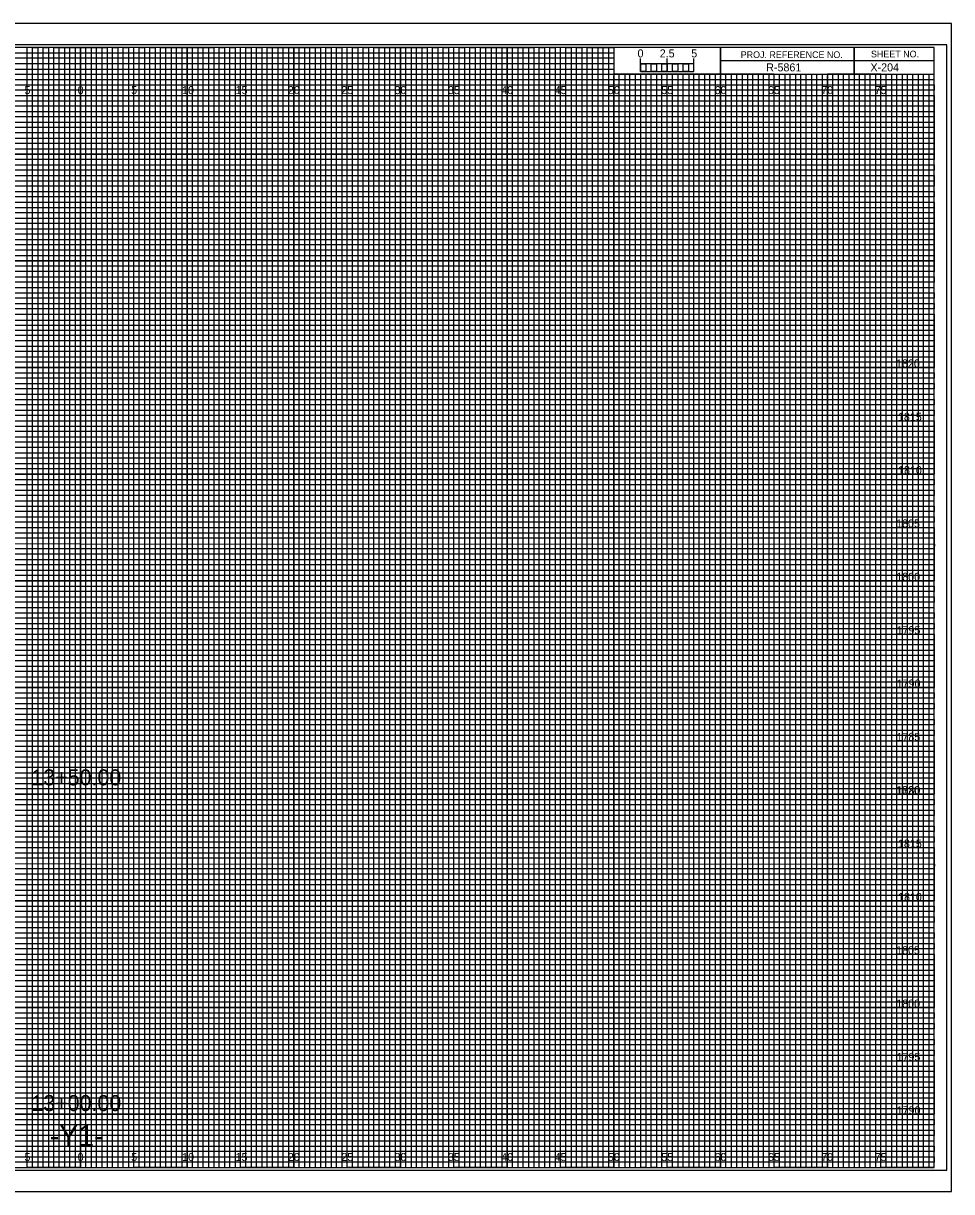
# Model space of a CAD drawing. Extents: x -7 to 162, y -2 to 767.
# Drawn here: x 74.6 to 161.7, y 327.7 to 437.2 of the extents above; entities that cross this region are included whole.
import ezdxf

# ---------------------------------------------------------------- set-up
doc = ezdxf.new("R2010")
doc.units = 0
for name, color, linetype in [('Prop Grid Mask', 7, 'Continuous'), ('Prop XS Alignment Label', 7, 'Continuous'), ('Prop XS Bar Scale Labels', 7, 'Continuous'), ('Prop XS Elevation Labels', 7, 'Continuous'), ('Prop XS Project Number', 7, 'Continuous'), ('Prop XS Sheet Number', 7, 'Continuous'), ('Prop XS Station Labels', 7, 'Continuous'), ('Sheet Cross Section CELL', 7, 'Continuous'), ('Sheet Cross Section Grid Major CELL', 7, 'Continuous'), ('Sheet Cross Section Grid Middle CELL', 7, 'Continuous'), ('Sheet Cross Section Grid Minor 1 CELL', 7, 'Continuous'), ('Sheet Cross Section Grid Minor 2 CELL', 7, 'Continuous'), ('Sheet Cross Section Scale CELL', 7, 'Continuous'), ('Sheet Cutting Line CELL', 7, 'Continuous'), ('Sheet DOT Grid CELL', 7, 'Continuous'), ('Sheet Plot Border Inside CELL', 7, 'Continuous'), ('Sheet Plot Border Outside CELL', 7, 'Continuous')]:
    doc.layers.add(name, color=color, linetype=linetype)

msp = doc.modelspace()

# ---------------------------------------------------------------- linework, layer by layer
at = {"layer": 'Sheet Cross Section CELL'}
for p, q in [((152.5, 435), (152.5, 432.5)), ((152.5, 432.5), (152.5, 435)), ((160, 433.75), (140, 433.75)), ((140, 433.75), (140, 432.5)), ((140, 432.5), (160, 432.5))]:
    msp.add_line(p, q, dxfattribs=at)
for points in [[(160, 435), (0, 435), (0, 330), (160, 330)], [(140, 435), (130, 435), (130, 432.51), (140, 432.51)], [(160, 435), (140, 435), (140, 432.5), (160, 432.5)]]:
    msp.add_lwpolyline(points, close=True, dxfattribs=at)
at = {"layer": 'Sheet Cross Section Grid Major CELL'}
for p, q in [((75, 435), (70, 435)), ((75, 330), (75, 435)), ((85, 435), (80, 435)), ((80, 435), (80, 330)), ((85, 330), (85, 435)), ((95, 435), (90, 435)), ((90, 435), (90, 330)), ((95, 330), (95, 435)), ((105, 435), (100, 435)), ((100, 435), (100, 330)), ((105, 330), (105, 435)), ((115, 435), (110, 435)), ((110, 435), (110, 330)), ((115, 330), (115, 435)), ((125, 435), (120, 435)), ((120, 435), (120, 330)), ((125, 330), (125, 435)), ((130, 435), (130, 330)), ((135, 330), (135, 432.5)), ((145, 432.5), (140, 432.5)), ((140, 432.5), (140, 330)), ((145, 330), (145, 432.5)), ((155, 432.5), (150, 432.5)), ((150, 432.5), (150, 330)), ((155, 330), (155, 432.5)), ((80, 330), (75, 330)), ((90, 330), (85, 330)), ((100, 330), (95, 330)), ((110, 330), (105, 330)), ((120, 330), (115, 330)), ((130, 330), (125, 330)), ((140, 330), (135, 330)), ((150, 330), (145, 330)), ((160, 330), (155, 330)), ((160, 330), (160, 330))]:
    msp.add_line(p, q, dxfattribs=at)
for points in [[(0, 430), (160, 430), (160, 425), (0, 425)], [(0, 420), (160, 420), (160, 415), (0, 415)], [(0, 410), (160, 410), (160, 405), (0, 405)], [(0, 400), (160, 400), (160, 395), (0, 395)], [(0, 390), (160, 390), (160, 385), (0, 385)], [(0, 380), (160, 380), (160, 375), (0, 375)], [(0, 370), (160, 370), (160, 365), (0, 365)], [(0, 360), (160, 360), (160, 355), (0, 355)], [(0, 350), (160, 350), (160, 345), (0, 345)], [(0, 340), (160, 340), (160, 335), (0, 335)]]:
    msp.add_lwpolyline(points, dxfattribs=at)
at = {"layer": 'Sheet Cross Section Grid Middle CELL'}
for points in [[(72.5, 330), (77.5, 330), (77.5, 435), (82.5, 435), (82.5, 330), (87.5, 330), (87.5, 435), (92.5, 435), (92.5, 330), (97.5, 330), (97.5, 435), (102.5, 435), (102.5, 330), (107.5, 330), (107.5, 435), (112.5, 435), (112.5, 330), (117.5, 330), (117.5, 435), (122.5, 435), (122.5, 330), (127.5, 330), (127.5, 435), (129.97, 435), (130, 435), (130, 432.5), (132.5, 432.5), (132.5, 330), (137.5, 330), (137.5, 432.5), (142.5, 432.5), (142.5, 330), (147.5, 330), (147.5, 432.5), (152.5, 432.5), (152.5, 330), (157.5, 330), (157.5, 432.5)], [(0, 432.5), (137.5, 432.5)], [(0, 422.5), (160, 422.5), (160, 427.5), (0, 427.5)], [(0, 412.5), (160, 412.5), (160, 417.5), (0, 417.5)], [(0, 402.5), (160, 402.5), (160, 407.5), (0, 407.5)], [(0, 392.5), (160, 392.5), (160, 397.5), (0, 397.5)], [(0, 382.5), (160, 382.5), (160, 387.5), (0, 387.5)], [(0, 372.5), (160, 372.5), (160, 377.5), (0, 377.5)], [(0, 362.5), (160, 362.5), (160, 367.5), (0, 367.5)], [(0, 352.5), (160, 352.5), (160, 357.5), (0, 357.5)], [(0, 342.5), (160, 342.5), (160, 347.5), (0, 347.5)], [(0, 332.5), (160, 332.5), (160, 337.5), (0, 337.5)]]:
    msp.add_lwpolyline(points, dxfattribs=at)
at = {"layer": 'Sheet Cross Section Grid Minor 1 CELL'}
for p, q in [((0, 434.5), (130, 434.5)), ((130, 433.99), (0, 433.99)), ((130, 434.5), (130, 433.99)), ((0, 433.5), (130, 433.5)), ((130, 432.94), (0, 432.94)), ((130, 433.5), (130, 432.94)), ((0, 432), (160, 432))]:
    msp.add_line(p, q, dxfattribs=at)
for points in [[(0, 431.5), (135, 431.5), (160, 431.5), (160, 431), (0, 431)], [(0, 430.5), (160, 430.5), (160, 429.5), (0, 429.5)], [(0, 429), (160, 429), (160, 428.5), (0, 428.49)], [(0, 428), (160, 428), (160, 427), (0, 427)], [(0, 426.5), (160, 426.5), (160, 426), (0, 426)], [(0, 425.5), (160, 425.5), (160, 424.5), (0, 424.5)], [(0, 424), (160, 424), (160, 423.5), (0, 423.5)], [(0, 423), (160, 423), (160, 422), (0, 422)], [(0, 421.5), (160, 421.5), (160, 421), (0, 421)], [(0, 420.5), (160, 420.5), (160, 419.5), (0, 419.5)], [(0, 419), (160, 419), (160, 418.5), (0, 418.5)], [(0, 418), (160, 418), (160, 416.98), (160, 416.5), (160, 416), (0, 416)], [(0, 417), (160, 417), (160, 416.5), (0, 416.5)], [(0, 415.5), (160, 415.5), (160, 414.5), (0, 414.51)], [(0, 414.51), (160, 414.5), (160, 414), (0, 414)], [(0, 413.5), (160, 413.5), (160, 413), (0, 413)], [(0, 412), (160, 412), (160, 411.5), (0, 411.5)], [(0, 411), (160, 411), (160, 410.5), (0, 410.5)], [(-0.04, 409.44), (160, 409.44), (160, 408.94), (-0.04, 408.94)], [(0, 408.5), (160, 408.5), (160, 408), (0, 408)], [(0, 407), (160, 407), (160, 406.5), (0, 406.5)], [(0, 406), (160, 406), (160, 405.5), (0, 405.5)], [(0, 404.5), (160, 404.5), (160, 404), (0, 404)], [(0, 403.5), (160, 403.5), (160, 403), (0, 403)], [(0, 402), (160, 402), (160, 401.5), (0, 401.5)], [(0, 401), (160, 401), (160, 400.5), (0, 400.5)], [(0, 399.5), (160, 399.5), (160, 398.99), (0, 399)], [(0, 398.5), (160, 398.5), (160, 398), (0, 398)], [(0, 397), (160, 397), (160, 396.5), (0, 396.5)], [(0, 396), (160, 396), (160, 395.5), (0, 395.5)], [(0, 394.5), (160, 394.5), (160, 394), (0, 394)], [(0, 393.5), (160, 393.5), (160, 393), (0, 393)], [(0, 392), (160, 392), (160, 391.5), (0, 391.5)], [(0, 391), (160, 391), (160, 390.5), (0, 390.5)], [(0, 389.5), (160, 389.5), (160, 389), (0, 389)], [(0, 388.5), (160.03, 388.45), (160, 388), (0, 388)], [(0, 387), (160, 387), (160, 386.5), (0, 386.5)], [(0, 386), (160, 386), (160, 385.5), (0, 385.5)], [(0, 384.5), (160, 384.5), (160, 384), (0, 384)], [(0, 383.5), (160, 383.5), (160, 383), (0, 383)], [(0, 382), (160, 382), (160, 381.5), (0, 381.5)], [(0, 381), (160, 381), (160, 380.5), (0, 380.5)], [(0, 379.5), (160, 379.5), (160, 379), (0, 379)], [(0, 378.5), (160, 378.5), (160, 378), (0, 378)], [(0, 377), (160, 377), (160, 376.5), (0, 376.5)], [(0, 376), (160, 376), (160, 375.5), (0, 375.5)], [(0, 374.5), (160, 374.5), (160, 374), (0, 374)], [(0, 373.5), (160, 373.5), (160, 373), (0, 373)], [(0, 372), (160, 372), (160, 371.5), (0, 371.5)], [(0, 371), (160, 371), (160, 370.5), (0, 370.5)], [(0, 369.5), (160, 369.5), (160, 368.99), (0, 369)], [(0, 368.5), (160, 368.5), (160, 368), (0, 368)], [(0, 367), (160, 367), (160, 366.5), (0, 366.5)], [(0, 366), (160, 366), (160, 365.5), (0, 365.5)], [(0, 364.5), (160, 364.5), (160, 364), (0, 364)], [(0, 363.5), (160, 363.5), (160, 363), (0, 363)], [(0, 362), (160, 362), (160, 361.5), (0, 361.5)], [(0, 361), (160, 361), (160, 360.5), (0, 360.5)], [(0, 359.5), (160, 359.5), (160, 359), (0, 359)], [(0, 358.5), (160.03, 358.45), (160, 358), (0, 358)], [(0, 357), (160, 357), (160, 356.5), (0, 356.5)], [(0, 356), (160, 356), (160, 355.5), (0, 355.5)], [(0, 354.5), (160, 354.5), (160, 354), (0, 354)], [(0, 353.5), (160, 353.5), (160, 353), (0, 353)], [(0, 352), (160, 352), (160, 351.5), (0, 351.5)], [(0, 351), (160, 351), (160, 350.5), (0, 350.5)], [(0, 349.5), (160, 349.5), (160, 349), (0, 349)], [(0, 348.5), (160, 348.5), (160, 348), (0, 348)], [(0, 347), (160, 347), (160, 346.5), (0, 346.5)], [(0, 346), (160, 346), (160, 345.5), (0, 345.5)], [(0, 344.5), (160, 344.5), (160, 344), (0, 344)], [(0, 343.5), (160, 343.5), (160, 343), (0, 343)], [(0, 342), (160, 342), (160, 341.5), (0, 341.5)], [(0, 341), (160, 341), (160, 340.5), (0, 340.5)], [(0, 339.5), (160, 339.5), (160, 339), (0, 339)], [(0, 338.5), (160, 338.5), (160, 338), (0, 338)], [(0, 337), (160, 337), (160, 336.5), (0, 336.5)], [(0, 336), (160, 336), (160, 335.5), (0, 335.5)], [(0, 334.5), (160, 334.5), (160, 334), (0, 334)], [(0, 333.5), (160, 333.5), (160, 333), (0, 333)], [(0, 332), (160, 332), (160, 331.5), (0, 331.5)], [(0, 331), (160, 331), (160, 330.5), (0, 330.5)]]:
    msp.add_lwpolyline(points, dxfattribs=at)
at = {"layer": 'Sheet Cross Section Grid Minor 2 CELL'}
for p, q in [((133.5, 432.5), (133, 432.5)), ((133, 432.5), (133, 330)), ((133.5, 330), (133.5, 432.5)), ((134.5, 432.5), (134, 432.5)), ((134, 432.5), (134, 330)), ((134.5, 330), (134.5, 432.5)), ((133, 330), (132.5, 330)), ((134, 330), (133.5, 330))]:
    msp.add_line(p, q, dxfattribs=at)
for points in [[(75, 330), (75.5, 330), (75.5, 435), (76, 435), (76, 330)], [(76, 330), (76.5, 330), (76.5, 435), (77, 435), (77, 330)], [(77.5, 330), (78, 330), (78, 435), (78.5, 435), (78.5, 330)], [(78.5, 330), (79, 330), (79, 435), (79.5, 435), (79.5, 330)], [(80, 330), (80.5, 330), (80.5, 435), (81, 435), (81, 330)], [(81, 330), (81.5, 330), (81.5, 435), (82, 435), (82, 330)], [(82.5, 330), (83, 330), (83, 435), (83.5, 435), (83.5, 330)], [(83.5, 330), (84, 330), (84, 435), (84.5, 435), (84.5, 330)], [(85, 330), (85.5, 330), (85.5, 435), (86, 435), (86, 330)], [(86, 330), (86.5, 330), (86.5, 435), (87, 435), (87, 330)], [(87.5, 330), (88, 330), (88, 435), (88.5, 435), (88.5, 330)], [(88.5, 330), (89, 330), (89, 435), (89.5, 435), (89.5, 330)], [(90, 330), (90.5, 330), (90.5, 435), (91, 435), (91, 330)], [(91, 330), (91.5, 330), (91.5, 435), (92, 435), (92, 330)], [(92.5, 330), (93, 330), (93, 435), (93.5, 435), (93.5, 330)], [(93.5, 330), (94, 330), (94, 435), (94.5, 435), (94.5, 330)], [(95, 330), (95.5, 330), (95.5, 435), (96, 435), (96, 330)], [(96, 330), (96.5, 330), (96.5, 435), (97, 435), (97, 330)], [(97.5, 330), (98, 330), (98, 435), (98.5, 435), (98.5, 330)], [(98.5, 330), (99, 330), (99, 435), (99.5, 435), (99.5, 330)], [(100, 330), (100.5, 330), (100.5, 435), (101, 435), (101, 330)], [(101, 330), (101.5, 330), (101.5, 435), (102, 435), (102, 330)], [(102.5, 330), (103, 330), (103, 435), (103.5, 435), (103.5, 330)], [(103.5, 330), (104, 330), (104, 435), (104.5, 435), (104.5, 330)], [(105, 330), (105.5, 330), (105.5, 435), (106, 435), (106, 330)], [(106, 330), (106.5, 330), (106.5, 435), (107, 435), (107, 330)], [(107.5, 330), (108, 330), (108, 435), (108.5, 435), (108.5, 330)], [(108.5, 330), (109, 330), (109, 435), (109.5, 435), (109.5, 330)], [(110, 330), (110.5, 330), (110.5, 435), (111, 435), (111, 330)], [(111, 330), (111.5, 330), (111.5, 435), (112, 435), (112, 330)], [(112.5, 330), (113, 330), (113, 435), (113.5, 435), (113.5, 330)], [(113.5, 330), (114, 330), (114, 435), (114.5, 435), (114.5, 330)], [(115, 330), (115.5, 330), (115.5, 435), (116, 435), (116, 330)], [(116, 330), (116.5, 330), (116.5, 435), (117, 435), (117, 330)], [(117.5, 330), (118, 330), (118, 435), (118.5, 435), (118.5, 330)], [(118.5, 330), (119, 330), (119, 435), (119.5, 435), (119.5, 330)], [(120, 330), (120.5, 330), (120.5, 435), (121, 435), (121, 330)], [(121, 330), (121.5, 330), (121.5, 435), (122, 435), (122, 330)], [(122.5, 330), (123, 330), (123, 435), (123.5, 435), (123.5, 330)], [(123.5, 330), (124, 330), (124, 435), (124.5, 435), (124.5, 330)], [(125, 330), (125.5, 330), (125.5, 435), (126, 435), (126, 330)], [(126, 330), (126.5, 330), (126.5, 435), (127, 435), (127, 330)], [(127.5, 330), (128, 330), (128, 435), (128.5, 435), (128.5, 330)], [(128.5, 330), (129, 330), (129, 435), (129.5, 435), (129.5, 330)], [(130, 330), (130.5, 330), (130.5, 432.5), (131.01, 432.5), (131.01, 330)], [(131, 330), (131.5, 330), (131.5, 432.5), (132, 432.5), (132, 330)], [(135, 330), (135.49, 330), (135.49, 432.5), (136, 432.5), (136, 330)], [(136, 330), (136.5, 330), (136.5, 432.5), (137.03, 432.5), (137.03, 330)], [(137.5, 330), (138, 330), (138, 432.5), (138.5, 432.5), (138.5, 330)], [(138.5, 330), (139, 330), (139, 432.5), (139.5, 432.5), (139.5, 330)], [(140, 330), (140.5, 330), (140.5, 432.5), (141, 432.5), (141, 330)], [(141, 330), (141.5, 330), (141.5, 432.5), (142, 432.5), (142, 330)], [(142.5, 330), (143, 330), (143, 432.5), (143.5, 432.5), (143.5, 330)], [(143.5, 330), (144, 330), (144, 432.5), (144.5, 432.5), (144.5, 330)], [(145, 330), (145.5, 330), (145.5, 432.5), (146, 432.5), (146, 330)], [(146, 330), (146.5, 330), (146.5, 432.5), (147, 432.5), (147, 330)], [(147.5, 330), (148, 330), (148, 432.5), (148.5, 432.5), (148.5, 330)], [(148.5, 330), (149, 330), (149, 432.5), (149.5, 432.5), (149.5, 330)], [(150, 330), (150.5, 330), (150.5, 432.5), (151, 432.5), (151, 330)], [(151, 330), (151.5, 330), (151.5, 432.5), (152, 432.5), (152, 330)], [(152.5, 330), (153, 330), (153, 432.5), (153.5, 432.5), (153.5, 330)], [(153.5, 330), (154, 330), (154, 432.5), (154.5, 432.5), (154.5, 330)], [(155, 330), (155.5, 330), (155.5, 432.5), (156, 432.5), (156, 330)], [(156, 330), (156.5, 330), (156.5, 432.5), (157, 432.5), (157, 330)], [(157.5, 330), (158, 330), (158, 432.5), (158.5, 432.5), (158.5, 330)], [(158.5, 330), (159, 330), (159, 432.5), (159.5, 432.5), (159.5, 330)]]:
    msp.add_lwpolyline(points, dxfattribs=at)
at = {"layer": 'Sheet Cross Section Scale CELL'}
for p, q in [((132.5, 432.75), (132.5, 433.95)), ((132.5, 433.45), (132.5, 433.95)), ((135, 432.75), (135, 433.95)), ((137.5, 432.75), (137.5, 433.95)), ((137.5, 433.45), (137.5, 433.95))]:
    msp.add_line(p, q, dxfattribs=at)
for points in [[(137.5, 433.45), (132.5, 433.45), (132.5, 432.75), (137.5, 432.75)], [(132.5, 433.45), (133, 433.45), (133, 432.75), (132.5, 432.75)], [(133.5, 433.45), (134, 433.45), (134, 432.75), (133.5, 432.75)], [(134.5, 433.45), (135, 433.45), (135, 432.75), (134.5, 432.75)], [(135.5, 433.45), (136, 433.45), (136, 432.75), (135.5, 432.75)], [(136.5, 433.45), (137, 433.45), (137, 432.75), (136.5, 432.75)]]:
    msp.add_lwpolyline(points, close=True, dxfattribs=at)
at = {"layer": 'Sheet Cutting Line CELL'}
for p, q in [((161.65, 437.25), (-6.7, 437.25)), ((-6.7, 327.75), (161.65, 327.75))]:
    msp.add_line(p, q, dxfattribs=at)
at = {"layer": 'Sheet DOT Grid CELL'}
for p, q in [((75, 330), (75, 435)), ((80, 330), (80, 435)), ((85, 330), (85, 435)), ((90, 330), (90, 435)), ((95, 330), (95, 435)), ((100, 330), (100, 435)), ((105, 330), (105, 435)), ((110, 330), (110, 435)), ((115, 330), (115, 435)), ((120, 330), (120, 435)), ((125, 330), (125, 435)), ((130, 330), (130, 432.34)), ((135, 330), (135, 432.34)), ((140, 330), (140, 432.34)), ((145, 330), (145, 432.34)), ((150, 330), (150, 432.34)), ((155, 330), (155, 432.34)), ((0, 430), (160, 430)), ((0, 425), (160, 425)), ((0, 420), (160, 420)), ((0, 415), (160, 415)), ((0, 410), (160, 410)), ((0, 405), (160, 405)), ((0, 400), (160, 400)), ((0, 395), (160, 395)), ((0, 390), (160, 390)), ((0, 385), (160, 385)), ((0, 380), (160, 380)), ((0, 375), (160, 375)), ((0, 370), (160, 370)), ((0, 365), (160, 365)), ((0, 360), (160, 360)), ((0, 355), (160, 355)), ((0, 350), (160, 350)), ((0, 345), (160, 345)), ((0, 340), (160, 340)), ((0, 335), (160, 335))]:
    msp.add_line(p, q, dxfattribs=at)
at = {"layer": 'Sheet Plot Border Inside CELL'}
msp.add_lwpolyline([(-5.4, 329.75), (161.2, 329.75), (161.2, 435.25), (-5.4, 435.25)], close=True, dxfattribs=at)
at = {"layer": 'Sheet Plot Border Outside CELL'}
msp.add_lwpolyline([(-6.7, 327.75), (161.65, 327.75), (161.65, 437.25), (-6.7, 437.25)], close=True, dxfattribs=at)

# ---------------------------------------------------------------- texts
at = {"layer": 'Prop Grid Mask'}
for s, p in [('5', (74.74, 430.62)), ('0', (79.73, 430.62)), ('0', (79.73, 430.62)), ('5', (84.74, 430.62)), ('10', (89.52, 430.62)), ('15', (94.53, 430.62)), ('20', (99.43, 430.62)), ('25', (104.44, 430.62)), ('30', (109.43, 430.62)), ('35', (114.44, 430.62)), ('40', (119.43, 430.62)), ('45', (124.44, 430.62)), ('50', (129.43, 430.62)), ('55', (134.44, 430.62)), ('60', (139.43, 430.62)), ('65', (144.44, 430.62)), ('70', (149.43, 430.62)), ('75', (154.44, 430.62)), ('5', (74.74, 330.62)), ('0', (79.73, 330.62)), ('0', (79.73, 330.62)), ('5', (84.74, 330.62)), ('10', (89.52, 330.62)), ('15', (94.53, 330.62)), ('20', (99.43, 330.62)), ('25', (104.44, 330.62)), ('30', (109.43, 330.62)), ('35', (114.44, 330.62)), ('40', (119.43, 330.62)), ('45', (124.44, 330.62)), ('50', (129.43, 330.62)), ('55', (134.44, 330.62)), ('60', (139.43, 330.62)), ('65', (144.44, 330.62)), ('70', (149.43, 330.62)), ('75', (154.44, 330.62))]:
    msp.add_text(s, height=0.75, dxfattribs=at).set_placement(p)
at = {"layer": 'Prop XS Alignment Label'}
msp.add_text('-Y1-', height=2, dxfattribs=at).set_placement((77.11, 332))
at = {"layer": 'Prop XS Bar Scale Labels'}
for s, p in [('2.5', (134.29, 434.06)), ('5', (137.24, 434.06))]:
    msp.add_text(s, height=0.75, dxfattribs=at).set_placement(p)
at = {"layer": 'Prop XS Elevation Labels'}
for s, p in [('1820', (156.44, 405)), ('1815', (156.62, 400)), ('1810', (156.63, 395)), ('1805', (156.45, 390)), ('1800', (156.46, 385)), ('1795', (156.49, 380)), ('1790', (156.5, 375)), ('1785', (156.48, 370)), ('1820', (156.44, 365)), ('1780', (156.49, 365)), ('1815', (156.62, 360)), ('1810', (156.63, 355)), ('1805', (156.45, 350)), ('1800', (156.46, 345)), ('1795', (156.49, 340)), ('1790', (156.5, 335))]:
    msp.add_text(s, height=0.75, dxfattribs=at).set_placement(p)
at = {"layer": 'Prop XS Project Number'}
msp.add_text('R-5861', height=0.75, dxfattribs=at).set_placement((144.27, 432.75))
at = {"layer": 'Prop XS Sheet Number'}
msp.add_text('X-204', height=0.75, dxfattribs=at).set_placement((154.04, 432.75))
at = {"layer": 'Prop XS Station Labels'}
for s, p in [('13+50.00', (75.39, 365.83)), ('13+00.00', (75.39, 335.3))]:
    msp.add_text(s, height=1.5, dxfattribs=at).set_placement(p)
at = {"layer": 'Sheet Cross Section CELL'}
for s, p in [('PROJ. REFERENCE NO.', (141.88, 434)), ('SHEET NO.', (154.09, 434.06))]:
    msp.add_text(s, height=0.625, dxfattribs=at).set_placement(p)
at = {"layer": 'Sheet Cross Section Scale CELL'}
msp.add_text('0', height=0.75, dxfattribs=at).set_placement((132.21, 434.06))

doc.saveas('drawing.dxf')
